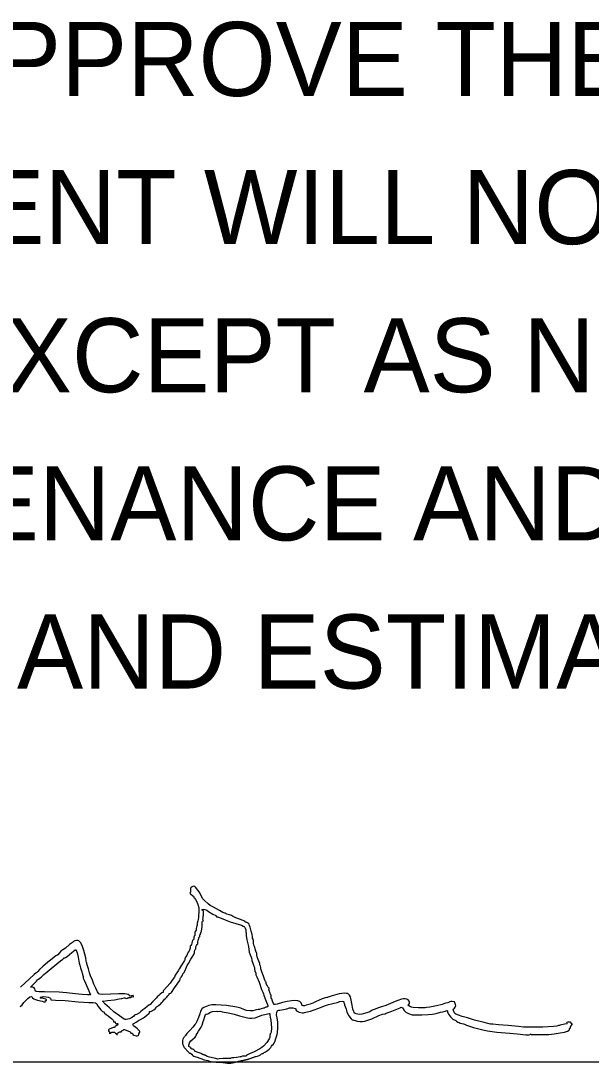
# Model space of a CAD drawing. Extents: x 0 to 34, y -2 to 22.
# Drawn here: x 25.628 to 26.706, y 3.055 to 5.025 of the extents above; entities that cross this region are included whole.
import ezdxf

# ---------------------------------------------------------------- set-up
doc = ezdxf.new("R2010")
doc.units = 0
for name, color, linetype in [('Default', 7, 'Continuous'), ('SH_Data', 7, 'Continuous'), ('SH_Text', 7, 'Continuous')]:
    doc.layers.add(name, color=color, linetype=linetype)

msp = doc.modelspace()

# ---------------------------------------------------------------- linework, layer by layer
at = {"layer": 'SH_Data'}
msp.add_line((24.5279, 3.0572), (28.0279, 3.0572), dxfattribs=at)
at = {"layer": 'SH_Text'}
for points in [[(26.0704, 3.0671), (26.0723, 3.0673), (26.0749, 3.0679), (26.078, 3.0691), (26.0807, 3.0706), (26.0818, 3.0718), (26.0824, 3.0723), (26.084, 3.0726), (26.0855, 3.0728), (26.0861, 3.0734), (26.0872, 3.0745), (26.0898, 3.0761), (26.0936, 3.0783), (26.0971, 3.0812), (26.0999, 3.0841), (26.1013, 3.0866), (26.1024, 3.0885), (26.1042, 3.0901), (26.1062, 3.0924), (26.1082, 3.0965), (26.1098, 3.101), (26.1105, 3.1047), (26.1112, 3.1069), (26.112, 3.1087), (26.1126, 3.1121), (26.1133, 3.1217), (26.113, 3.1322), (26.1118, 3.1402), (26.1108, 3.1462), (26.1114, 3.1509), (26.1123, 3.1526), (26.1136, 3.1539), (26.1152, 3.1547), (26.1172, 3.155), (26.1237, 3.1559), (26.13, 3.1576), (26.1353, 3.1589), (26.1414, 3.159), (26.146, 3.1582), (26.1472, 3.1575), (26.1472, 3.1566), (26.1472, 3.1553), (26.1485, 3.1538), (26.1534, 3.1513), (26.1594, 3.1498), (26.1619, 3.1499), (26.1637, 3.1505), (26.169, 3.1518), (26.1751, 3.1529), (26.189, 3.1581), (26.2033, 3.1633), (26.209, 3.1655), (26.2146, 3.1667), (26.2198, 3.1677), (26.2255, 3.1694), (26.2307, 3.1709), (26.2347, 3.1715), (26.2372, 3.1711), (26.2378, 3.1706), (26.238, 3.1698), (26.2383, 3.1685), (26.2389, 3.1676), (26.2394, 3.167), (26.2393, 3.1662), (26.2395, 3.1646), (26.2406, 3.1619), (26.2424, 3.1566), (26.2428, 3.1543), (26.244, 3.1512), (26.2478, 3.1443), (26.2521, 3.1385), (26.2538, 3.1368), (26.255, 3.1365), (26.2594, 3.135), (26.2634, 3.1339), (26.2683, 3.1333), (26.2733, 3.1334), (26.2775, 3.1341), (26.2836, 3.1359), (26.291, 3.1387), (26.3045, 3.1445), (26.3112, 3.1471), (26.316, 3.1481), (26.3183, 3.1488), (26.3216, 3.1501), (26.3288, 3.1529), (26.3383, 3.1569), (26.3446, 3.1595), (26.3461, 3.1602), (26.3478, 3.16), (26.3492, 3.1591), (26.3501, 3.1576), (26.3519, 3.154), (26.3553, 3.1509), (26.3603, 3.1483), (26.367, 3.1462), (26.374, 3.1457), (26.3858, 3.1458), (26.3976, 3.1464), (26.4049, 3.1472), (26.4093, 3.1479), (26.4146, 3.1488), (26.4205, 3.1507), (26.4243, 3.1515), (26.4296, 3.1528), (26.4335, 3.154), (26.4341, 3.1533), (26.4342, 3.1517), (26.4347, 3.1496), (26.4358, 3.1472), (26.4397, 3.142), (26.4443, 3.1377), (26.4465, 3.1364), (26.4484, 3.1359), (26.4497, 3.1354), (26.4512, 3.1342), (26.4538, 3.1324), (26.4558, 3.1313), (26.4578, 3.1302), (26.4611, 3.1295), (26.4643, 3.1289), (26.4659, 3.1281), (26.4698, 3.1264), (26.4833, 3.122), (26.5006, 3.1177), (26.5098, 3.1156), (26.5272, 3.1131), (26.5519, 3.1111), (26.5657, 3.1099), (26.582, 3.1084), (26.5879, 3.1084), (26.5906, 3.1091), (26.5913, 3.1099), (26.5921, 3.1091), (26.5983, 3.1085), (26.6114, 3.1085), (26.6258, 3.109), (26.6354, 3.11), (26.6469, 3.112), (26.655, 3.1135), (26.6607, 3.1152), (26.664, 3.1171), (26.6646, 3.118), (26.6646, 3.119), (26.6647, 3.1199), (26.6656, 3.1206), (26.6665, 3.1214), (26.6666, 3.1224), (26.6668, 3.1238), (26.6678, 3.1254), (26.6694, 3.1279), (26.6694, 3.1287), (26.6687, 3.129), (26.668, 3.1295), (26.6675, 3.1307), (26.6665, 3.1321), (26.664, 3.1324), (26.6618, 3.1321), (26.6599, 3.1312), (26.6591, 3.1303), (26.66, 3.1298), (26.6602, 3.1296), (26.6593, 3.1292), (26.6555, 3.1281), (26.6473, 3.1264), (26.6452, 3.1261), (26.6438, 3.1255), (26.6408, 3.1248), (26.6342, 3.124), (26.6142, 3.1229), (26.5926, 3.1224), (26.5779, 3.1229), (26.5681, 3.1241), (26.5488, 3.1255), (26.5305, 3.1273), (26.5199, 3.1281), (26.5153, 3.1284), (26.5126, 3.129), (26.5032, 3.1316), (26.485, 3.1357), (26.4772, 3.1382), (26.4716, 3.1403), (26.4616, 3.1429), (26.4546, 3.1455), (26.4496, 3.1472), (26.448, 3.1482), (26.4464, 3.1512), (26.4451, 3.1543), (26.4448, 3.1562), (26.4455, 3.1575), (26.4473, 3.1587), (26.4488, 3.1605), (26.4495, 3.1631), (26.4493, 3.1655), (26.4488, 3.1674), (26.4482, 3.1688), (26.4472, 3.1704), (26.4427, 3.1711), (26.4404, 3.1712), (26.4382, 3.1703), (26.4345, 3.1689), (26.4305, 3.1677), (26.424, 3.1658), (26.4131, 3.1632), (26.4067, 3.1616), (26.4008, 3.1607), (26.3942, 3.1597), (26.3921, 3.1592), (26.3886, 3.1589), (26.379, 3.159), (26.3694, 3.1599), (26.366, 3.1605), (26.3641, 3.1613), (26.361, 3.1632), (26.3599, 3.1638), (26.3603, 3.1648), (26.362, 3.1673), (26.3624, 3.1697), (26.3616, 3.172), (26.3598, 3.174), (26.3573, 3.1755), (26.3543, 3.1764), (26.3509, 3.1764), (26.3473, 3.1754), (26.3404, 3.1728), (26.3352, 3.1712), (26.3175, 3.1637), (26.3095, 3.1612), (26.3017, 3.1585), (26.2971, 3.1567), (26.2919, 3.1545), (26.2869, 3.1518), (26.2818, 3.1497), (26.2723, 3.1472), (26.268, 3.1468), (26.2643, 3.147), (26.2612, 3.1479), (26.2589, 3.1494), (26.257, 3.1515), (26.2566, 3.1524), (26.2568, 3.1528), (26.2562, 3.1538), (26.2548, 3.1566), (26.2537, 3.1641), (26.2522, 3.1739), (26.2508, 3.1797), (26.2489, 3.1832), (26.2459, 3.186), (26.2434, 3.1865), (26.2391, 3.1866), (26.234, 3.1862), (26.2294, 3.1854), (26.2157, 3.1817), (26.2085, 3.1793), (26.207, 3.1788), (26.2059, 3.1789), (26.203, 3.1783), (26.1974, 3.176), (26.186, 3.171), (26.1808, 3.1684), (26.1747, 3.1663), (26.1668, 3.164), (26.1635, 3.163), (26.1609, 3.163), (26.1591, 3.1639), (26.1584, 3.1656), (26.1572, 3.1688), (26.1547, 3.1711), (26.1508, 3.1725), (26.1456, 3.173), (26.1391, 3.1727), (26.1312, 3.1714), (26.1222, 3.1693), (26.1118, 3.1662), (26.1084, 3.1654), (26.1063, 3.1657), (26.1048, 3.1676), (26.1035, 3.1715), (26.102, 3.1759), (26.1008, 3.1781), (26.1003, 3.1792), (26.1005, 3.1811), (26.1006, 3.183), (26.1001, 3.1837), (26.0993, 3.1846), (26.0987, 3.1869), (26.097, 3.192), (26.0963, 3.1937), (26.0968, 3.1949), (26.0972, 3.1961), (26.0959, 3.1975), (26.0945, 3.199), (26.094, 3.2004), (26.0936, 3.2015), (26.0926, 3.2022), (26.0917, 3.2033), (26.0915, 3.2054), (26.0913, 3.2077), (26.0902, 3.209), (26.0892, 3.21), (26.0887, 3.2114), (26.087, 3.2172), (26.0823, 3.2292), (26.0813, 3.2329), (26.0812, 3.2346), (26.0812, 3.2357), (26.0803, 3.2378), (26.0793, 3.2404), (26.0791, 3.2427), (26.0783, 3.2459), (26.0763, 3.2507), (26.0742, 3.2555), (26.0737, 3.2585), (26.0734, 3.2616), (26.0719, 3.266), (26.0703, 3.2704), (26.0696, 3.2735), (26.0693, 3.2752), (26.0686, 3.2762), (26.0678, 3.2778), (26.0675, 3.2815), (26.0672, 3.2857), (26.0664, 3.2887), (26.0656, 3.2911), (26.0653, 3.2939), (26.0645, 3.2979), (26.0628, 3.3039), (26.0613, 3.3115), (26.06, 3.3149), (26.059, 3.3175), (26.0581, 3.3185), (26.0558, 3.3199), (26.0533, 3.321), (26.0523, 3.321), (26.0518, 3.3211), (26.0507, 3.3221), (26.0491, 3.3234), (26.0461, 3.325), (26.0342, 3.3296), (26.0275, 3.3327), (26.0254, 3.3335), (26.0219, 3.3347), (26.0167, 3.3364), (26.0155, 3.3367), (26.015, 3.3373), (26.0143, 3.3379), (26.0129, 3.3382), (26.011, 3.3385), (26.0095, 3.3394), (26.0031, 3.3431), (25.9918, 3.3492), (25.9852, 3.3529), (25.9817, 3.3558), (25.9748, 3.3618), (25.9713, 3.3654), (25.969, 3.3699), (25.9671, 3.374), (25.9645, 3.3785), (25.9578, 3.3873), (25.9562, 3.3885), (25.9545, 3.3889), (25.9527, 3.3888), (25.9511, 3.388), (25.9496, 3.3868), (25.9485, 3.3851), (25.9479, 3.3832), (25.9479, 3.381), (25.9479, 3.3782), (25.9473, 3.3768), (25.9472, 3.3759), (25.9483, 3.3744), (25.9525, 3.3711), (25.9537, 3.3701), (25.9542, 3.369), (25.9547, 3.3676), (25.9559, 3.3662), (25.9577, 3.364), (25.9599, 3.3598), (25.9616, 3.3562), (25.9626, 3.3524), (25.9631, 3.3499), (25.9637, 3.3493), (25.9639, 3.3483), (25.964, 3.3445), (25.9635, 3.3302), (25.9629, 3.3263), (25.962, 3.3239)], [(25.6271, 3.1613), (25.6277, 3.1627), (25.6287, 3.1633), (25.6297, 3.1637), (25.6302, 3.1648), (25.633, 3.169), (25.6362, 3.1725), (25.6407, 3.177), (25.6447, 3.1799), (25.6475, 3.1808), (25.6484, 3.1804), (25.6486, 3.1794), (25.6496, 3.1778), (25.652, 3.1762), (25.6554, 3.1747), (25.6591, 3.1738), (25.6676, 3.1715), (25.6711, 3.1705), (25.6735, 3.1704), (25.6745, 3.1711), (25.6741, 3.1727), (25.674, 3.1731), (25.6745, 3.1729), (25.6753, 3.1728), (25.676, 3.1733), (25.676, 3.1744), (25.6748, 3.1755), (25.6725, 3.1762), (25.6696, 3.1766), (25.6648, 3.1776), (25.6639, 3.1782), (25.665, 3.1785), (25.6656, 3.1788), (25.6655, 3.1795), (25.6653, 3.1801), (25.6663, 3.1794), (25.6673, 3.1788), (25.6677, 3.1792), (25.6683, 3.1799), (25.6699, 3.1804), (25.6755, 3.18), (25.6794, 3.1791), (25.682, 3.1781), (25.6836, 3.1769), (25.684, 3.1754), (25.6841, 3.1745), (25.6851, 3.174), (25.6929, 3.1739), (25.7114, 3.1731), (25.7359, 3.1706), (25.7561, 3.1695), (25.7641, 3.1692), (25.7685, 3.1687), (25.7705, 3.1676), (25.771, 3.1659), (25.7739, 3.1618), (25.7788, 3.1555), (25.7807, 3.1534), (25.782, 3.1524), (25.7835, 3.1515), (25.7857, 3.1494), (25.7889, 3.1463), (25.7923, 3.1439), (25.7992, 3.1386), (25.8022, 3.1359), (25.8027, 3.1349), (25.8027, 3.134), (25.8026, 3.1327), (25.8042, 3.1326), (25.8056, 3.1325), (25.806, 3.1317), (25.8062, 3.1305), (25.807, 3.1294), (25.808, 3.1287), (25.8088, 3.129), (25.8095, 3.1297), (25.8102, 3.1298), (25.8108, 3.1293), (25.811, 3.1283), (25.8101, 3.1267), (25.8079, 3.1252), (25.8058, 3.124), (25.8049, 3.1229), (25.8042, 3.1222), (25.8023, 3.1218), (25.7976, 3.1201), (25.7947, 3.1188), (25.7932, 3.1174), (25.7931, 3.1158), (25.7944, 3.1138), (25.7957, 3.1122), (25.7953, 3.1116), (25.7947, 3.1114), (25.7947, 3.1111), (25.7955, 3.1109), (25.7964, 3.1114), (25.7992, 3.1129), (25.8021, 3.1134), (25.8047, 3.1129), (25.8067, 3.1115), (25.8093, 3.1091), (25.81, 3.109), (25.8097, 3.1099), (25.8102, 3.1111), (25.8121, 3.1125), (25.8145, 3.1136), (25.8165, 3.1139), (25.8176, 3.1139), (25.8175, 3.1149), (25.8173, 3.1157), (25.8176, 3.1157), (25.8187, 3.1158), (25.8207, 3.1169), (25.8222, 3.118), (25.8235, 3.1182), (25.8276, 3.1165), (25.8331, 3.1142), (25.8341, 3.1137), (25.8349, 3.1124), (25.8356, 3.1112), (25.8367, 3.1111), (25.8377, 3.1111), (25.8384, 3.1104), (25.8394, 3.1089), (25.8411, 3.1077), (25.8454, 3.1063), (25.8475, 3.1063), (25.8492, 3.1067), (25.8502, 3.1076), (25.8503, 3.109), (25.8504, 3.1104), (25.8513, 3.1116), (25.8523, 3.1129), (25.8526, 3.1145), (25.8521, 3.1158), (25.8509, 3.1166), (25.8497, 3.1172), (25.8492, 3.1181), (25.8479, 3.1197), (25.8449, 3.122), (25.8407, 3.1251), (25.8397, 3.1264), (25.8394, 3.1276), (25.8399, 3.1287), (25.841, 3.1297), (25.8455, 3.132), (25.8475, 3.1331), (25.8483, 3.134), (25.85, 3.1353), (25.8539, 3.1373), (25.8596, 3.1402), (25.8653, 3.145), (25.8696, 3.1487), (25.8704, 3.15), (25.8705, 3.1509), (25.8705, 3.1521), (25.8715, 3.152), (25.8727, 3.152), (25.8744, 3.1527), (25.8786, 3.1551), (25.8823, 3.1582), (25.8834, 3.1597), (25.8839, 3.1608), (25.8843, 3.1616), (25.8851, 3.162), (25.8864, 3.1624), (25.8875, 3.1635), (25.8902, 3.1657), (25.8912, 3.1664), (25.8939, 3.1695), (25.896, 3.1711), (25.8977, 3.1735), (25.8991, 3.1754), (25.9009, 3.1768), (25.903, 3.1785), (25.9056, 3.1818), (25.9074, 3.184), (25.9078, 3.1853), (25.908, 3.186), (25.9092, 3.1864), (25.9108, 3.1871), (25.912, 3.1884), (25.9181, 3.1967), (25.9229, 3.2038), (25.9255, 3.2075), (25.9278, 3.2111), (25.9287, 3.2133), (25.9288, 3.2146), (25.9291, 3.2156), (25.9308, 3.2173), (25.9327, 3.2194), (25.9334, 3.2215), (25.9336, 3.223), (25.934, 3.2236), (25.9355, 3.2256), (25.9379, 3.23), (25.9402, 3.2348), (25.9412, 3.2378), (25.9419, 3.2394), (25.9446, 3.2433), (25.9488, 3.2509), (25.9512, 3.2548), (25.9545, 3.2603), (25.9555, 3.2632), (25.9559, 3.2656), (25.9563, 3.268), (25.9573, 3.2696), (25.9581, 3.2709), (25.9581, 3.2723), (25.9583, 3.2742), (25.9593, 3.2768), (25.9607, 3.279), (25.9619, 3.28), (25.9623, 3.2839), (25.9625, 3.2867), (25.963, 3.2878), (25.9635, 3.2886), (25.9637, 3.2903), (25.9641, 3.2923), (25.965, 3.2933), (25.9657, 3.2941), (25.9658, 3.2955), (25.9657, 3.2969), (25.9663, 3.2978), (25.9671, 3.2985), (25.9672, 3.2992), (25.9681, 3.303), (25.9687, 3.3043), (25.9695, 3.3087), (25.9703, 3.3129), (25.9703, 3.3168), (25.9703, 3.3218), (25.971, 3.323), (25.9722, 3.3234), (25.973, 3.3237), (25.9724, 3.3247), (25.9718, 3.3264), (25.9719, 3.329), (25.9721, 3.3313), (25.9724, 3.3331), (25.9728, 3.3336), (25.9729, 3.3362), (25.9725, 3.3414), (25.9719, 3.343), (25.9701, 3.3439), (25.9697, 3.3453), (25.9723, 3.3456), (25.9754, 3.345), (25.9789, 3.3435), (25.9825, 3.3412), (25.9907, 3.3364), (25.9961, 3.3336), (25.9969, 3.3329), (25.9969, 3.3322), (25.997, 3.3316), (25.9974, 3.3314), (25.9995, 3.3313), (26.0029, 3.3302), (26.0137, 3.3256), (26.0234, 3.3215), (26.0336, 3.3183), (26.0446, 3.3152), (26.0479, 3.3138), (26.0502, 3.312), (26.0516, 3.3096), (26.0525, 3.3064), (26.0535, 3.2961), (26.0547, 3.2875), (26.0567, 3.2804), (26.0578, 3.2752), (26.0594, 3.2645), (26.0608, 3.2596), (26.0634, 3.2538), (26.0644, 3.2487), (26.0647, 3.2468), (26.0652, 3.2458), (26.0666, 3.242), (26.0684, 3.2369), (26.0691, 3.2352), (26.0692, 3.2338), (26.0692, 3.232), (26.0701, 3.2294), (26.0714, 3.2244), (26.072, 3.2217), (26.0735, 3.218), (26.0778, 3.2075), (26.0827, 3.1939), (26.0852, 3.1886), (26.0861, 3.1858), (26.0867, 3.1834), (26.0893, 3.1765), (26.0933, 3.1665), (26.0943, 3.1638), (26.0941, 3.1618), (26.0928, 3.1606), (26.0904, 3.1602), (26.0883, 3.1594), (26.0874, 3.1587), (26.0859, 3.1585), (26.0815, 3.1572), (26.0789, 3.1563), (26.076, 3.1559), (26.0732, 3.1555), (26.0706, 3.1546), (26.0662, 3.1535), (26.0603, 3.1534), (26.0541, 3.1544), (26.049, 3.1562), (26.0434, 3.1584), (26.0355, 3.1604), (26.016, 3.1635), (25.9964, 3.1649), (25.9885, 3.1647), (25.9828, 3.1638), (25.9731, 3.16), (25.9701, 3.1581), (25.969, 3.1566), (25.9687, 3.1554), (25.9681, 3.1546), (25.9674, 3.153), (25.9657, 3.1479), (25.9633, 3.1411), (25.9602, 3.1336), (25.958, 3.1298), (25.9563, 3.1276), (25.9551, 3.1255), (25.9526, 3.1224), (25.9468, 3.1164), (25.941, 3.1104), (25.9386, 3.107), (25.9383, 3.106), (25.9378, 3.1055), (25.9366, 3.1046), (25.9351, 3.1023), (25.9339, 3.0997), (25.9333, 3.0975), (25.9334, 3.0913), (25.9342, 3.0887), (25.9351, 3.0866), (25.9364, 3.0839), (25.9445, 3.0754), (25.9464, 3.0738), (25.9476, 3.0734), (25.9486, 3.0732), (25.949, 3.0726), (25.9494, 3.0719), (25.9503, 3.0717), (25.9512, 3.0713), (25.9516, 3.0704), (25.9519, 3.0695), (25.9525, 3.0691), (25.9548, 3.0678), (25.9563, 3.0669), (25.9581, 3.0665), (25.9606, 3.0658), (25.9661, 3.0639), (25.9699, 3.0628), (25.972, 3.0615), (25.9739, 3.0606), (25.9776, 3.06), (25.9813, 3.0595)], [(25.96, 3.3137), (25.9596, 3.3123), (25.959, 3.3083), (25.9587, 3.3063), (25.9571, 3.3032), (25.9562, 3.3015), (25.9562, 3.2997), (25.9561, 3.296), (25.9551, 3.2947), (25.9546, 3.293), (25.9547, 3.2911), (25.9545, 3.2891), (25.9529, 3.287), (25.9512, 3.2846), (25.9507, 3.2816), (25.9503, 3.2788), (25.949, 3.2772), (25.9478, 3.2759), (25.9473, 3.2741), (25.9475, 3.2722), (25.9461, 3.2685), (25.9459, 3.267), (25.9438, 3.2643), (25.9427, 3.2618), (25.9413, 3.2583), (25.939, 3.2551), (25.9377, 3.2515), (25.9374, 3.2501), (25.9366, 3.2489), (25.9314, 3.2399), (25.9277, 3.2333), (25.9247, 3.2289), (25.9221, 3.2255), (25.9203, 3.2227), (25.9191, 3.2208), (25.9186, 3.2191), (25.9177, 3.217), (25.9156, 3.214), (25.9125, 3.2097), (25.9097, 3.2057), (25.8973, 3.1921), (25.8966, 3.1911), (25.8967, 3.1896), (25.8968, 3.1882), (25.8958, 3.1883), (25.8939, 3.1878), (25.8911, 3.1849), (25.8885, 3.1822), (25.8867, 3.1811), (25.8856, 3.1804), (25.8835, 3.1776), (25.8761, 3.1703), (25.8717, 3.1653), (25.8715, 3.1649), (25.8709, 3.165), (25.8692, 3.1643), (25.8663, 3.1618), (25.862, 3.1578), (25.8579, 3.1553), (25.854, 3.1518), (25.8518, 3.1498), (25.8503, 3.1489), (25.8495, 3.1487), (25.8492, 3.1482), (25.8483, 3.1475), (25.8461, 3.1468), (25.8438, 3.1461), (25.8425, 3.1452), (25.8408, 3.1433), (25.8384, 3.1414), (25.8327, 3.1386), (25.8268, 3.1372), (25.8244, 3.1372), (25.8226, 3.1379), (25.8139, 3.144), (25.8034, 3.1517), (25.7948, 3.1593), (25.7863, 3.1668), (25.7847, 3.1681), (25.7841, 3.1694), (25.7837, 3.1703), (25.783, 3.1709), (25.7821, 3.1715), (25.7833, 3.1721), (25.7915, 3.1729), (25.8048, 3.1741), (25.8132, 3.176), (25.8185, 3.1771), (25.8231, 3.178), (25.8241, 3.1781), (25.8253, 3.1776), (25.8267, 3.1771), (25.8283, 3.1775)], [(25.8327, 3.1789), (25.8347, 3.179), (25.8369, 3.1797), (25.839, 3.1805), (25.8399, 3.18), (25.8402, 3.1798), (25.8404, 3.1809), (25.8401, 3.1824), (25.839, 3.1825), (25.8339, 3.1814), (25.8329, 3.1816), (25.8327, 3.1822), (25.8321, 3.1834), (25.8305, 3.1843), (25.824, 3.1854), (25.8129, 3.1857), (25.7971, 3.1851), (25.7818, 3.1847), (25.7771, 3.1849), (25.7749, 3.1854), (25.7726, 3.1892), (25.769, 3.1964), (25.7656, 3.2037), (25.7641, 3.2078), (25.7629, 3.2112), (25.7591, 3.2195), (25.7575, 3.2253), (25.7562, 3.2301), (25.7551, 3.2332), (25.7534, 3.2383), (25.7525, 3.2424), (25.7525, 3.2433), (25.752, 3.244), (25.7513, 3.2451), (25.7511, 3.2471), (25.7503, 3.2534), (25.7468, 3.2677), (25.744, 3.275), (25.7415, 3.2807), (25.7409, 3.2822), (25.7392, 3.284), (25.7372, 3.2856), (25.7352, 3.2866), (25.7327, 3.2865), (25.7296, 3.2858), (25.727, 3.2846), (25.7259, 3.2834), (25.7249, 3.2826), (25.7194, 3.2787), (25.7118, 3.272), (25.7067, 3.2687), (25.7034, 3.2662), (25.7002, 3.2626), (25.6975, 3.2596), (25.6956, 3.2583), (25.6934, 3.2574), (25.6902, 3.255), (25.6834, 3.2495), (25.6786, 3.2456), (25.669, 3.2373), (25.663, 3.2318), (25.6595, 3.2279), (25.658, 3.2261), (25.6567, 3.2253), (25.6525, 3.222), (25.644, 3.2138), (25.6271, 3.198)], [(25.9451, 3.0894), (25.9455, 3.0898), (25.9455, 3.0911), (25.9465, 3.0933), (25.949, 3.0965), (25.9569, 3.104), (25.9581, 3.1055), (25.9589, 3.1077), (25.9605, 3.1109), (25.9634, 3.115), (25.9661, 3.1186), (25.9672, 3.1208), (25.9683, 3.1226), (25.9702, 3.1262), (25.9721, 3.1333), (25.9731, 3.1368), (25.975, 3.1429), (25.9765, 3.1468), (25.9773, 3.1474), (25.9786, 3.1474), (25.9808, 3.1478), (25.9831, 3.1494), (25.9858, 3.1512), (25.9895, 3.1521), (25.9979, 3.1527), (25.9999, 3.1524), (26.0051, 3.1528), (26.0079, 3.1519), (26.0117, 3.1508), (26.0163, 3.1501), (26.0228, 3.1492), (26.0306, 3.1472), (26.041, 3.1443), (26.0557, 3.14), (26.0598, 3.1395), (26.0642, 3.1395), (26.0706, 3.1403), (26.0756, 3.1422), (26.083, 3.1451), (26.097, 3.1486), (26.0976, 3.1487), (26.098, 3.1483), (26.0983, 3.1455), (26.0988, 3.1413), (26.0999, 3.1361), (26.101, 3.1289), (26.1012, 3.1208), (26.1005, 3.1138), (26.0999, 3.1115), (26.0991, 3.1103), (26.0985, 3.109), (26.0983, 3.1068), (26.0979, 3.1038), (26.0967, 3.1006), (26.0924, 3.0936), (26.0863, 3.087), (26.0829, 3.0842), (26.0794, 3.082), (26.0685, 3.0762), (26.0598, 3.0724), (26.056, 3.0706), (26.054, 3.069), (26.0526, 3.0679), (26.0496, 3.068), (26.0465, 3.0681), (26.0449, 3.067), (26.0439, 3.0662), (26.0432, 3.0664), (26.0419, 3.0667), (26.0391, 3.066), (26.035, 3.0651), (26.03, 3.0647), (26.0261, 3.0645), (26.0245, 3.0639), (26.0236, 3.0634), (26.0212, 3.0635), (26.0183, 3.0636)], [(25.9695, 3.0721), (25.9682, 3.0726), (25.9627, 3.0747), (25.9571, 3.0769), (25.9563, 3.0771), (25.9563, 3.0777), (25.956, 3.0786), (25.9547, 3.0798), (25.9529, 3.0808), (25.9512, 3.0812), (25.9499, 3.0819), (25.9488, 3.0834), (25.9477, 3.0849), (25.9465, 3.0852)], [(26.0136, 3.0633), (26.0102, 3.0633), (26.0021, 3.0625), (25.9998, 3.0624), (25.9981, 3.0629), (25.9961, 3.0637), (25.9927, 3.0642), (25.9839, 3.0659), (25.98, 3.0672), (25.978, 3.0683), (25.977, 3.069)]]:
    msp.add_lwpolyline(points, dxfattribs=at)
msp.add_lwpolyline([(25.7534, 3.1838), (25.7433, 3.1847), (25.7311, 3.1858), (25.7137, 3.1877), (25.6997, 3.1885), (25.6724, 3.1892), (25.6624, 3.1895), (25.6572, 3.19), (25.6551, 3.1909), (25.6547, 3.1927), (25.6541, 3.195), (25.6524, 3.1968), (25.6502, 3.198), (25.6477, 3.1981), (25.6464, 3.198), (25.6464, 3.1987), (25.652, 3.2044), (25.657, 3.2095), (25.6591, 3.2121), (25.6597, 3.2129), (25.6611, 3.2135), (25.6636, 3.215), (25.6668, 3.2179), (25.671, 3.2219), (25.6773, 3.2273), (25.6884, 3.237), (25.7025, 3.248), (25.7068, 3.2514), (25.7085, 3.2533), (25.7089, 3.2538), (25.7098, 3.2537), (25.7109, 3.2536), (25.7118, 3.2542), (25.7148, 3.2565), (25.7236, 3.2637), (25.7302, 3.2691), (25.7316, 3.2695), (25.732, 3.2684), (25.7337, 3.2633), (25.7359, 3.2551), (25.7376, 3.2436), (25.7387, 3.2396), (25.7405, 3.2347), (25.7419, 3.229), (25.7427, 3.2274), (25.7433, 3.2245), (25.7445, 3.2202), (25.7452, 3.2183), (25.7453, 3.217), (25.7456, 3.215), (25.747, 3.2117), (25.7544, 3.1955), (25.7589, 3.184)], close=True, dxfattribs=at)
for points in [[(25.962, 3.3239), (25.9615, 3.3219), (25.9611, 3.3203), (25.9607, 3.3178), (25.9607, 3.3152), (25.96, 3.3137)], [(25.8283, 3.1775), (25.8301, 3.178), (25.8313, 3.1784), (25.8327, 3.1789)], [(25.9465, 3.0852), (25.9449, 3.0861), (25.9449, 3.0873), (25.9449, 3.0885), (25.9451, 3.0894)], [(25.977, 3.069), (25.9754, 3.0697), (25.9731, 3.0704), (25.9715, 3.071), (25.9695, 3.0721)], [(25.9813, 3.0595), (25.9864, 3.0571), (25.9954, 3.0568), (26.0054, 3.0567), (26.0097, 3.0561), (26.0187, 3.0547), (26.0238, 3.0546), (26.0311, 3.0563), (26.0354, 3.0572), (26.0392, 3.0582), (26.043, 3.059), (26.0528, 3.061), (26.0616, 3.0635), (26.0704, 3.0671)], [(26.0183, 3.0636), (26.0162, 3.0633), (26.0148, 3.0633), (26.0136, 3.0633)]]:
    msp.add_open_spline(points, degree=2, dxfattribs=at)

# ---------------------------------------------------------------- texts
at = {"layer": 'Default'}
for s, p in [('I HEREBY APPROVE THESE PLANS AND DECLARE THAT THE MAKING OF THIS ', (24.5279, 4.8827)), ('IMPROVEMENT WILL NOT REQUIRE THE CLOSING TO TRAFFIC OF THE ', (24.5279, 4.6027)), ('HIGHWAY EXCEPT AS NOTED ON SHEET 06, AND THAT PROVISIONS FOR ', (24.5279, 4.3227)), ('THE MAINTENANCE AND SAFETY OF TRAFFIC WILL BE AS SET FORTH ON ', (24.5279, 4.0427)), ('THE PLANS AND ESTIMATES. ', (24.5279, 3.7627))]:
    msp.add_text(s, height=0.14, dxfattribs=at).set_placement(p)

doc.saveas('drawing.dxf')
